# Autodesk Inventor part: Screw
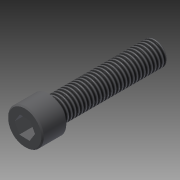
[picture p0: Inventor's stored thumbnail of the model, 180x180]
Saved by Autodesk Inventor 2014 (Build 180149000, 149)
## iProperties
Created: 2006-07
Part Number: Screw
Material: system_material_0
Description: SCREW, CAP, 1/4-20 X 3/8
Document SubType Name: Modeling
Designer: Z.MCGILL
Engineer: SAP
Manufacturer: Standard
Standards Organization: Custom
Mass: 26.2447 g
Surface Area: 18.9522 cm^2
Volume: 3.34682 cm^3
Density: 7.84168 g/cm^3
Appearance: system_RenderingStyle_0
NetWeight: 0.005
WeightUOM: KG
ModelCode: Comp
Author: Z.MCGILL
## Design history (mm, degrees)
node "SHCS"
body "Solid1"
tag "TaggingFeature2"
feature "DerivedBody::SHCS"
other parameters: "Thread_Length" = 57.15, "Head_Chamfer" = 0.635, "Thread_Chamfer" = 0.2286, "Thread_Diameter" = 12.7, "Head_Diameter" = 19.05, "Head_Length" = 12.7, "Hex_Head_Width" = 9.525, "Hex_Head_Depth" = 9.525, "d23" = 0, "d24" = 0
